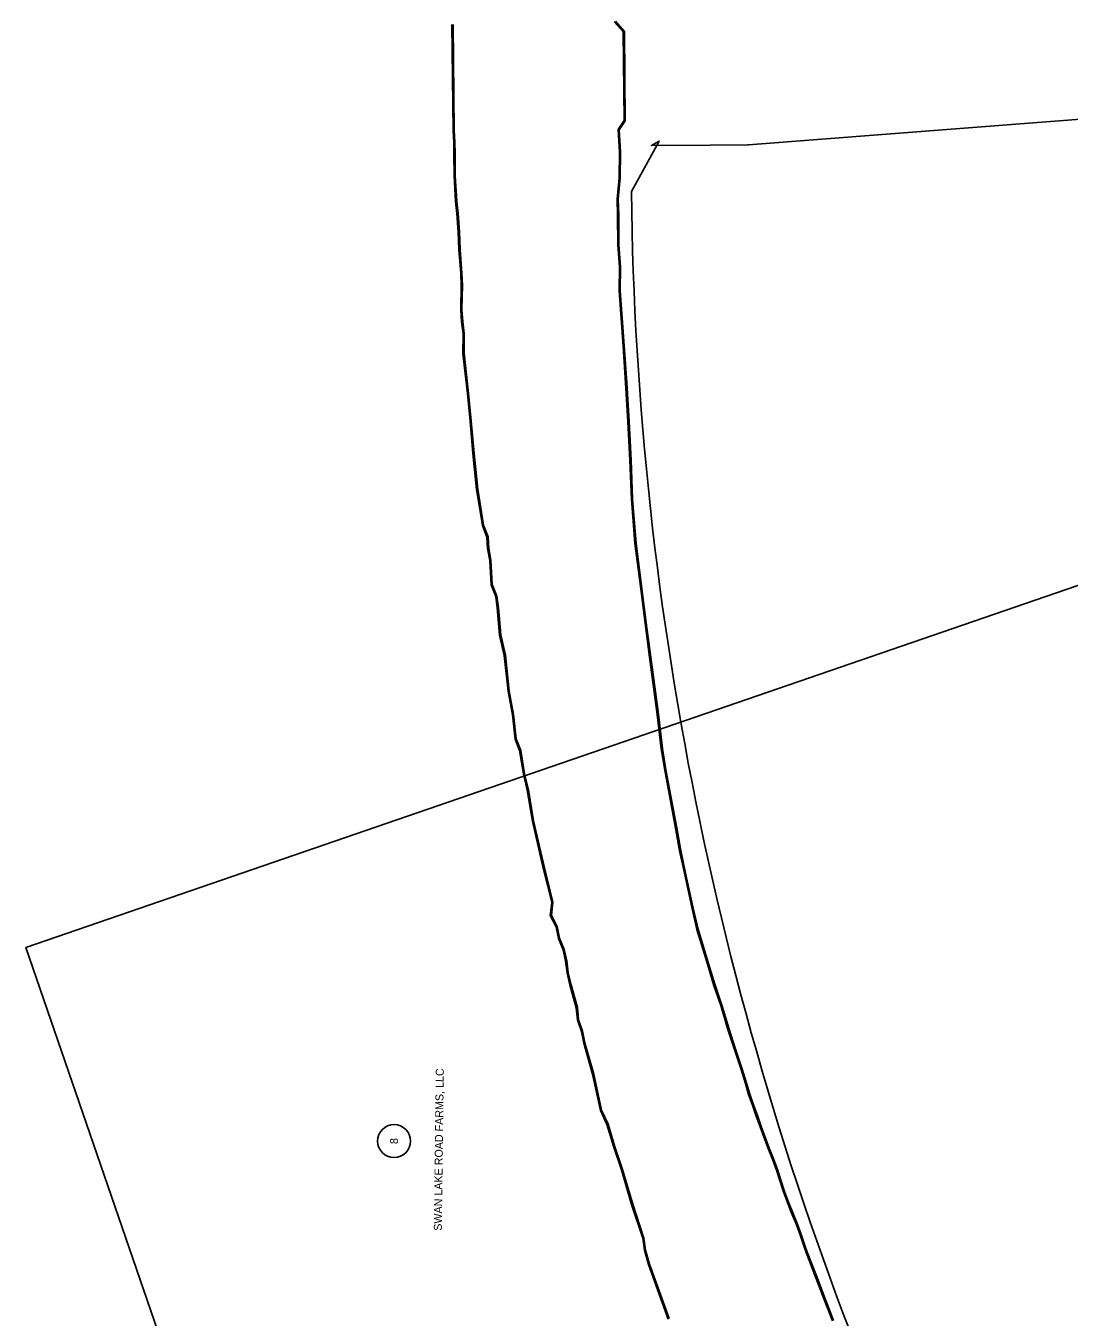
# Model space of a CAD drawing. Extents: x 20504422 to 20508365, y 7965199 to 7983597.
# Drawn here: x 20504612 to 20506384, y 7976636 to 7978830 of the extents above; entities that cross this region are included whole.
import ezdxf

# ---------------------------------------------------------------- set-up
doc = ezdxf.new("R2010")
doc.units = 0
for name, color, linetype in [('SurControl', 7, 'Continuous'), ('SurRipRap', 7, 'Continuous'), ('SurTopOfWater', 7, 'Continuous'), ('SurTreeLineRight', 7, 'Continuous')]:
    doc.layers.add(name, color=color, linetype=linetype)

msp = doc.modelspace()

# ---------------------------------------------------------------- linework, layer by layer
at = {"layer": 'SurControl'}
msp.add_circle((20505237.4, 7976935.1), 28, dxfattribs=at)
at = {"layer": 'SurRipRap'}
msp.add_lwpolyline([(20505629.6, 7974306.3), (20507520.7, 7974957.1), (20506503, 7977914.7), (20504611.9, 7977263.9)], close=True, dxfattribs=at)
at = {"layer": 'SurTopOfWater'}
for points in [[(20505335.8, 7978832), (20505337.7, 7978651.9), (20505338.9, 7978631.9), (20505339.1, 7978612.1), (20505339.5, 7978574.8), (20505342, 7978531.2), (20505344.2, 7978510.8), (20505346.5, 7978479.7), (20505347.7, 7978449.8), (20505350.7, 7978409), (20505351.5, 7978388.9), (20505350.9, 7978347.9), (20505352.3, 7978327), (20505354.8, 7978306.9), (20505354.5, 7978273.2), (20505362, 7978204.8), (20505366, 7978164.2), (20505371.3, 7978103.1), (20505377.8, 7978042), (20505387.7, 7977980.5), (20505395.2, 7977961.2), (20505396.5, 7977941.5), (20505400.1, 7977921.4), (20505402.3, 7977879.9), (20505410.1, 7977860), (20505412.8, 7977840.9), (20505416.8, 7977794.5), (20505424.8, 7977759.9), (20505431.1, 7977699.2), (20505438.6, 7977659.1), (20505443.1, 7977617.8), (20505450.8, 7977598.3), (20505457.2, 7977558.6), (20505463.8, 7977531.2), (20505472.4, 7977478.5), (20505490.9, 7977398.9), (20505505.3, 7977340.7), (20505502.7, 7977318.4), (20505512.9, 7977298.7), (20505516.7, 7977279), (20505524.8, 7977259.8), (20505529, 7977240.9), (20505531.5, 7977220.6), (20505536.3, 7977200.2), (20505546.9, 7977161.3), (20505549.2, 7977140.7), (20505555.9, 7977121), (20505559.8, 7977101.2), (20505574.7, 7977048.4), (20505588, 7976986.8), (20505599.2, 7976963.2), (20505610.9, 7976924.6), (20505623.7, 7976885.9), (20505641, 7976827.3), (20505660.2, 7976769.8), (20505662.9, 7976749.5), (20505669.6, 7976725.4), (20505703.2, 7976632.5)], [(20505337.8, 7978832), (20505339.7, 7978651.9), (20505340.9, 7978632), (20505341.1, 7978612.1), (20505341.5, 7978574.9), (20505344, 7978531.4), (20505346.2, 7978510.9), (20505348.5, 7978479.9), (20505349.7, 7978449.9), (20505352.7, 7978409.1), (20505353.5, 7978388.9), (20505352.9, 7978347.9), (20505354.3, 7978327.2), (20505356.8, 7978307.1), (20505356.5, 7978273.3), (20505364, 7978205), (20505368, 7978164.4), (20505373.3, 7978103.3), (20505379.8, 7978042.2), (20505389.7, 7977981.1), (20505397.2, 7977961.6), (20505398.5, 7977941.7), (20505402.1, 7977921.6), (20505404.3, 7977880.3), (20505412, 7977860.6), (20505414.8, 7977841.1), (20505418.8, 7977794.8), (20505426.8, 7977760.2), (20505433.1, 7977699.5), (20505440.6, 7977659.4), (20505445, 7977618.3), (20505452.7, 7977598.8), (20505459.1, 7977558.9), (20505465.8, 7977531.6), (20505474.4, 7977478.9), (20505492.8, 7977399.3), (20505507.4, 7977340.9), (20505504.7, 7977318.8), (20505514.8, 7977299.4), (20505518.6, 7977279.5), (20505526.7, 7977260.5), (20505531, 7977241.3), (20505533.5, 7977220.9), (20505538.3, 7977200.7), (20505548.9, 7977161.7), (20505551.1, 7977141.1), (20505557.8, 7977121.6), (20505561.8, 7977101.7), (20505576.7, 7977048.9), (20505589.9, 7976987.4), (20505601.1, 7976963.9), (20505612.8, 7976925.2), (20505625.6, 7976886.5), (20505642.9, 7976827.9), (20505662.1, 7976770.3), (20505664.9, 7976749.9), (20505671.5, 7976726), (20505705, 7976633.3)], [(20505611.6, 7978836.6), (20505626.9, 7978819.4), (20505628.3, 7978668.6), (20505618.2, 7978653.6), (20505620.4, 7978615.1), (20505619.9, 7978571.4), (20505616.3, 7978535.2), (20505617.3, 7978507.9), (20505617.4, 7978457.5), (20505620.4, 7978420.3), (20505619.9, 7978379.3), (20505622.5, 7978340.6), (20505626.5, 7978285.5), (20505630.9, 7978223.2), (20505634.8, 7978157.4), (20505638.2, 7978091.5), (20505640.8, 7978025.6), (20505646.6, 7977950.6), (20505656.5, 7977873.1), (20505664, 7977815), (20505671.5, 7977756.8), (20505684.5, 7977659.7), (20505691.4, 7977601.4), (20505697.4, 7977565.2), (20505715.8, 7977466.6), (20505722.6, 7977428.1), (20505731, 7977389.9), (20505743.2, 7977332.4), (20505752.1, 7977294.5), (20505767, 7977245.3), (20505780.4, 7977200.8), (20505793.1, 7977163.7), (20505804.1, 7977126.1), (20505816.5, 7977089), (20505822.4, 7977070.3), (20505827.1, 7977056.4), (20505834.5, 7977033), (20505839.9, 7977014.2), (20505846.2, 7976995.9), (20505852.8, 7976977.5), (20505859.4, 7976959.1), (20505873, 7976922.5), (20505880.2, 7976904.3), (20505887.2, 7976885.8), (20505892.3, 7976869.5), (20505899.1, 7976848.6), (20505905.8, 7976830.4), (20505912.9, 7976812.3), (20505920.6, 7976794.3), (20505927.5, 7976775.8), (20505933.7, 7976757.2), (20505937.4, 7976745.8), (20505954.2, 7976702.6), (20505968.2, 7976666.1), (20505982.1, 7976629.7)], [(20505613.7, 7978837.3), (20505628.9, 7978820.2), (20505630.3, 7978668), (20505620.2, 7978653), (20505622.4, 7978615.2), (20505621.9, 7978571.3), (20505618.3, 7978535.2), (20505619.3, 7978507.9), (20505619.4, 7978457.6), (20505622.4, 7978420.4), (20505621.9, 7978379.4), (20505624.5, 7978340.7), (20505628.5, 7978285.7), (20505632.9, 7978223.3), (20505636.8, 7978157.5), (20505640.2, 7978091.6), (20505642.8, 7978025.7), (20505648.6, 7977950.8), (20505658.4, 7977873.4), (20505666, 7977815.2), (20505673.5, 7977757), (20505686.5, 7977660), (20505693.3, 7977601.7), (20505699.3, 7977565.5), (20505717.7, 7977467), (20505724.6, 7977428.5), (20505732.9, 7977390.3), (20505745.1, 7977332.9), (20505754, 7977295), (20505768.9, 7977245.8), (20505782.3, 7977201.5), (20505795, 7977164.3), (20505806, 7977126.7), (20505818.4, 7977089.6), (20505824.3, 7977071), (20505829, 7977057.1), (20505836.4, 7977033.5), (20505841.8, 7977014.8), (20505848.1, 7976996.6), (20505854.7, 7976978.2), (20505861.3, 7976959.8), (20505874.9, 7976923.2), (20505882, 7976905), (20505889, 7976886.5), (20505894.2, 7976870.1), (20505901, 7976849.3), (20505907.7, 7976831.1), (20505914.8, 7976813.1), (20505922.4, 7976795), (20505929.4, 7976776.5), (20505935.6, 7976757.8), (20505939.2, 7976746.5), (20505956.1, 7976703.3), (20505970.1, 7976666.8), (20505984, 7976630.4)]]:
    msp.add_lwpolyline(points, dxfattribs=at)
at = {"layer": 'SurTreeLineRight'}
msp.add_lwpolyline([(20505640.8, 7978548.2), (20505687.7, 7978633.9), (20505674.6, 7978626.1), (20505774.6, 7978626.9), (20505838.5, 7978627.3), (20505839.6, 7978627.4), (20506814, 7978702.6), (20506813, 7978702.6), (20508157.1, 7978709.8)], dxfattribs=at)
msp.add_arc((20511205.4, 7978611.7), 5565, 180.6542, 202.8501, dxfattribs=at)

# ---------------------------------------------------------------- texts
at = {"layer": 'SurControl'}
for s, p in [('SWAN LAKE ROAD FARMS, LLC', (20505318.6, 7976782.6)), ('8', (20505244.2, 7976929.9))]:
    msp.add_text(s, height=13.6, rotation=89.2974, dxfattribs=at).set_placement(p)

doc.saveas('drawing.dxf')
